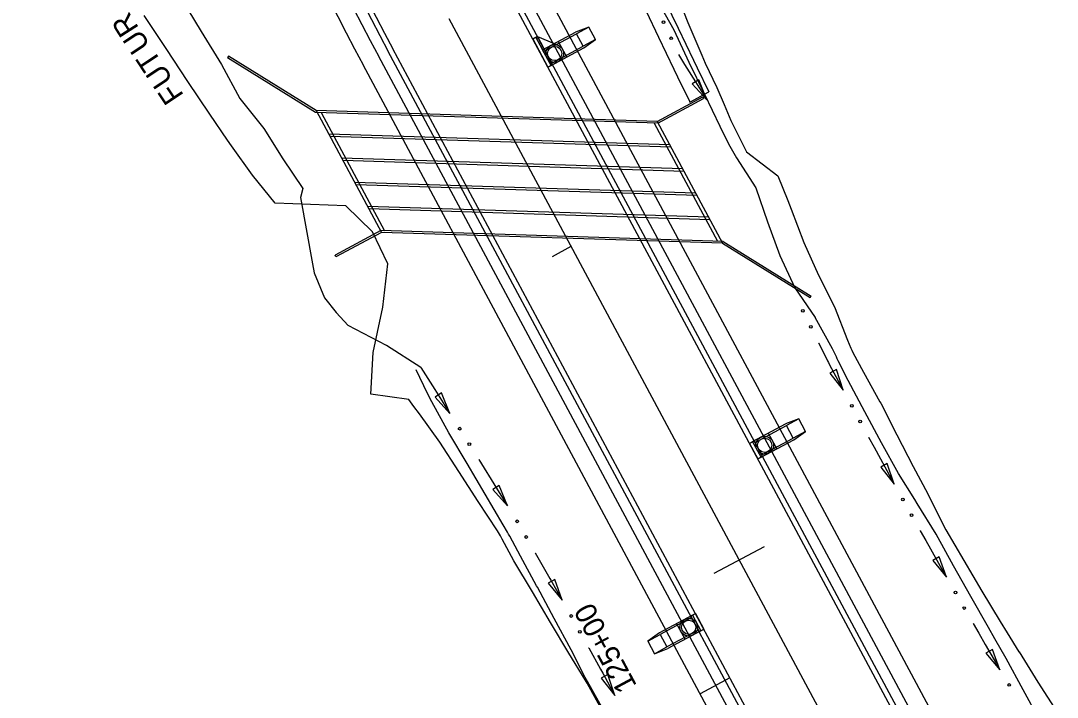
# Model space of a CAD drawing. Extents: x 979959 to 994833, y 1835619 to 1845316.
# Drawn here: x 992472.4 to 992763.9, y 1841250.8 to 1841441.1 of the extents above; entities that cross this region are included whole.
import ezdxf

# ---------------------------------------------------------------- set-up
doc = ezdxf.new("R2010")
doc.units = 0
for name, color, linetype in [('Future 5 Lane Construction Limits', 7, 'Continuous'), ('R_Drainage', 7, 'Continuous'), ('R_Horz Alg', 7, 'Continuous'), ('R_Horz Alg Stationing', 7, 'Continuous'), ('R_Proposed Const Limits', 7, 'Continuous'), ('R_Proposed Road', 7, 'Continuous'), ('R_Special Ditch', 7, 'Continuous')]:
    doc.layers.add(name, color=color, linetype=linetype)

msp = doc.modelspace()

# ---------------------------------------------------------------- linework, layer by layer
at = {"layer": 'Future 5 Lane Construction Limits'}
for points in [[(992631, 1841510.9), (992632.44, 1841501.52), (992636.1, 1841493.15), (992638.98, 1841484.37), (992641.67, 1841475.45), (992643.86, 1841468.2), (992644.48, 1841466.3), (992647.7, 1841456.68), (992651.16, 1841447.19), (992656.08, 1841438.48), (992660.28, 1841429.38), (992664.69, 1841420.4), (992669, 1841411.37), (992671.46, 1841406.41), (992673.66, 1841402.52), (992679.08, 1841394.08), (992682.42, 1841384.52), (992685.84, 1841375.01), (992690.13, 1841365.96), (992695.81, 1841357.66)], [(992581.51, 1841334.6), (992570.85, 1841336.06), (992571.49, 1841347.75), (992572.72, 1841353.48), (992574.19, 1841360.54), (992575.68, 1841372.69), (992571.33, 1841381.7), (992563.83, 1841389.03), (992544, 1841389.75), (992537.6, 1841397.66), (992531.71, 1841405.85), (992530.57, 1841407.47), (992525.58, 1841414.75), (992519.42, 1841423.97), (992513.27, 1841433.23), (992507.09, 1841442.53)], [(992758.91, 1841244.47), (992754.31, 1841252.9), (992749.53, 1841261.73), (992746.36, 1841267.28), (992744.53, 1841270.47), (992739.6, 1841279.15), (992734.71, 1841287.83), (992729.85, 1841296.69), (992724.5, 1841305.33), (992723.79, 1841306.46), (992719.26, 1841313.73), (992714.49, 1841322.33), (992709.8, 1841331.11), (992705.11, 1841339.89), (992702.31, 1841345.42), (992702.04, 1841345.98), (992701.77, 1841346.55), (992700.65, 1841348.83), (992695.81, 1841357.66)], [(992640.53, 1841238.67), (992636.4, 1841246.3), (992631.71, 1841254.81), (992631.15, 1841255.72), (992626.52, 1841263.21), (992621.4, 1841271.89), (992616.28, 1841280.46), (992611.03, 1841289.24), (992607.77, 1841295.28), (992607.35, 1841296.2), (992607.34, 1841296.2), (992606.47, 1841297.62), (992601.08, 1841305.92), (992595.61, 1841314.31), (992590.23, 1841322.53), (992584.52, 1841330.5), (992582.98, 1841332.59), (992581.51, 1841334.6)]]:
    msp.add_lwpolyline(points, dxfattribs=at)
at = {"layer": 'R_Drainage'}
for p, q in [((992619.17, 1841432.87), (992628.43, 1841437.83)), ((992632.19, 1841439.28), (992628.43, 1841437.83)), ((992632.19, 1841439.28), (992628.66, 1841437.39)), ((992634.08, 1841435.76), (992632.19, 1841439.28)), ((992617.28, 1841436.4), (992621.53, 1841428.47)), ((992621.53, 1841428.47), (992617.28, 1841436.4)), ((992617.72, 1841436.63), (992623.54, 1841434.15)), ((992617.72, 1841436.63), (992622.43, 1841434.62)), ((992619.85, 1841432.67), (992628.66, 1841437.39)), ((992623.58, 1841435.24), (992625.94, 1841430.83)), ((992630.55, 1841433.87), (992628.66, 1841437.39)), ((992634.08, 1841435.76), (992630.55, 1841433.87)), ((992630.78, 1841433.42), (992634.08, 1841435.76)), ((992621.74, 1841429.14), (992619.85, 1841432.67)), ((992621.53, 1841428.47), (992630.78, 1841433.42)), ((992621.74, 1841429.14), (992630.55, 1841433.87)), ((992530.82, 1841431.08), (992530.55, 1841430.65)), ((992555.31, 1841415.3), (992530.55, 1841430.65)), ((992555.46, 1841415.8), (992530.82, 1841431.08)), ((992660.59, 1841418.2), (992665.88, 1841421.04)), ((992651.41, 1841412.77), (992664.19, 1841419.62)), ((992651.53, 1841412.26), (992664.43, 1841419.18)), ((992664.19, 1841419.62), (992664.43, 1841419.18)), ((992651.53, 1841412.26), (992555.31, 1841415.3)), ((992555.46, 1841415.8), (992573.83, 1841381.53)), ((992651.41, 1841412.77), (992555.46, 1841415.8)), ((992556.89, 1841415.25), (992574.71, 1841382.01)), ((992650.53, 1841412.3), (992668.35, 1841379.05)), ((992651.41, 1841412.77), (992669.78, 1841378.51)), ((992654.96, 1841406.15), (992559.01, 1841409.18)), ((992655.32, 1841405.48), (992559.37, 1841408.5)), ((992658.6, 1841399.37), (992562.65, 1841402.4)), ((992658.96, 1841398.69), (992563.01, 1841401.72)), ((992662.23, 1841392.58), (992566.28, 1841395.61)), ((992662.6, 1841391.91), (992566.65, 1841394.93)), ((992665.87, 1841385.8), (992569.92, 1841388.83)), ((992666.24, 1841385.12), (992570.28, 1841388.15)), ((992573.71, 1841382.04), (992560.81, 1841375.12)), ((992573.83, 1841381.53), (992561.05, 1841374.68)), ((992669.93, 1841379), (992573.71, 1841382.04)), ((992669.78, 1841378.51), (992573.83, 1841381.53)), ((992669.78, 1841378.51), (992694.43, 1841363.22)), ((992669.93, 1841379), (992694.69, 1841363.65)), ((992561.05, 1841374.68), (992560.81, 1841375.12)), ((992694.43, 1841363.22), (992694.69, 1841363.65)), ((992678.23, 1841322.71), (992687.48, 1841327.67)), ((992678.9, 1841322.5), (992687.72, 1841327.23)), ((992691.24, 1841329.12), (992687.48, 1841327.67)), ((992691.24, 1841329.12), (992687.72, 1841327.23)), ((992689.61, 1841323.7), (992687.72, 1841327.23)), ((992693.13, 1841325.59), (992691.24, 1841329.12)), ((992682.63, 1841325.07), (992685, 1841320.66)), ((992693.13, 1841325.59), (992689.61, 1841323.7)), ((992689.84, 1841323.26), (992693.13, 1841325.59)), ((992678.67, 1841322.94), (992677.34, 1841322.23)), ((992680.59, 1841318.3), (992678.23, 1841322.71)), ((992680.79, 1841318.98), (992678.9, 1841322.5)), ((992680.59, 1841318.3), (992689.84, 1841323.26)), ((992680.79, 1841318.98), (992689.61, 1841323.7)), ((992661.27, 1841273.91), (992652.02, 1841268.95)), ((992661.07, 1841273.23), (992652.25, 1841268.51)), ((992661.07, 1841273.23), (992662.96, 1841269.71)), ((992661.27, 1841273.91), (992663.63, 1841269.5)), ((992652.02, 1841268.95), (992648.73, 1841266.62)), ((992662.96, 1841269.71), (992654.14, 1841264.98)), ((992663.63, 1841269.5), (992654.38, 1841264.54)), ((992659.22, 1841267.14), (992656.86, 1841271.54)), ((992663.19, 1841269.26), (992664.51, 1841269.97)), ((992648.73, 1841266.62), (992652.25, 1841268.51)), ((992648.73, 1841266.62), (992650.62, 1841263.09)), ((992652.25, 1841268.51), (992654.14, 1841264.98)), ((992650.62, 1841263.09), (992654.14, 1841264.98)), ((992650.62, 1841263.09), (992654.38, 1841264.54))]:
    msp.add_line(p, q, dxfattribs=at)
for points in [[(992613.97, 1841543.61), (992618.65, 1841535.4), (992621.39, 1841526.27), (992624.19, 1841517.55), (992627.16, 1841508.86), (992627.89, 1841506.81), (992630.28, 1841500.24), (992633.57, 1841491.66), (992637.02, 1841483.14), (992640.64, 1841474.68), (992644.5, 1841466.09), (992648.71, 1841457.03), (992652.96, 1841447.97), (992653.76, 1841446.27), (992657.24, 1841438.94), (992661.57, 1841429.93), (992662.61, 1841427.78), (992665.88, 1841421.04)], [(992660.59, 1841418.2), (992660.54, 1841418.31), (992657.21, 1841425.16), (992656.16, 1841427.32), (992651.83, 1841436.36), (992648.34, 1841443.7), (992647.53, 1841445.42), (992643.27, 1841454.49), (992639.04, 1841463.6), (992635.14, 1841472.27), (992631.48, 1841480.83), (992627.99, 1841489.46), (992624.66, 1841498.14), (992622.24, 1841504.78), (992621.49, 1841506.88), (992618.5, 1841515.66), (992615.66, 1841524.49), (992613.1, 1841533.02), (992608.61, 1841540.89)], [(992677.34, 1841322.23), (992679.71, 1841317.83), (992681.03, 1841318.54), (992678.67, 1841322.94)], [(992664.51, 1841269.97), (992662.15, 1841274.38), (992660.83, 1841273.67), (992663.19, 1841269.26)]]:
    msp.add_lwpolyline(points, dxfattribs=at)
for points in [[(992617.72, 1841436.63), (992621.98, 1841428.7), (992620.65, 1841427.99), (992616.4, 1841435.93)], [(992621.98, 1841428.7), (992617.72, 1841436.63), (992616.4, 1841435.93), (992620.65, 1841427.99)], [(992623.58, 1841435.24), (992625.94, 1841430.83), (992621.53, 1841428.47), (992619.17, 1841432.87)], [(992682.63, 1841325.07), (992685, 1841320.66), (992680.59, 1841318.3), (992678.23, 1841322.71)], [(992678.67, 1841322.94), (992681.03, 1841318.54), (992679.71, 1841317.83), (992677.34, 1841322.23)], [(992659.22, 1841267.14), (992656.86, 1841271.54), (992661.27, 1841273.91), (992663.63, 1841269.5)], [(992663.19, 1841269.26), (992660.83, 1841273.67), (992662.15, 1841274.38), (992664.51, 1841269.97)]]:
    msp.add_lwpolyline(points, close=True, dxfattribs=at)
for centre, radius in [((992622.56, 1841431.85), 2.5), ((992622.56, 1841431.85), 2.5), ((992622.56, 1841431.85), 2), ((992622.56, 1841431.85), 2), ((992681.61, 1841321.69), 2.5), ((992681.61, 1841321.69), 2.5), ((992681.61, 1841321.69), 2), ((992681.61, 1841321.69), 2), ((992660.25, 1841270.52), 2.5), ((992660.25, 1841270.52), 2.5), ((992660.25, 1841270.52), 2), ((992660.25, 1841270.52), 2)]:
    msp.add_circle(centre, radius, dxfattribs=at)
at = {"layer": 'R_Horz Alg'}
msp.add_line((992721.09, 1841202.52), (992592.92, 1841441.62), dxfattribs=at)
at = {"layer": 'R_Horz Alg Stationing'}
for points in [[(992621.94, 1841374.79), (992627.23, 1841377.63)], [(992667.42, 1841285.71), (992681.52, 1841293.27)]]:
    msp.add_lwpolyline(points, dxfattribs=at)
at = {"layer": 'R_Proposed Const Limits'}
for points in [[(992472.41, 1841535.7), (992476.48, 1841525.43), (992481.41, 1841515.48), (992486.58, 1841505.66), (992491.29, 1841495.7), (992496.3, 1841485.89), (992501.34, 1841476.12), (992506.36, 1841466.36), (992511.51, 1841456.69), (992512.89, 1841454.45), (992517.48, 1841447.42), (992523.16, 1841438.06), (992528.82, 1841428.72), (992534, 1841419.16), (992540.79, 1841410.71), (992546.09, 1841402.21), (992551.77, 1841393.91)], [(992656.3, 1841449.94), (992660.01, 1841440.59), (992663.9, 1841431.33), (992664.89, 1841429.14), (992668.11, 1841422.24), (992670.26, 1841417.53), (992672.08, 1841413.01), (992676.49, 1841404.16), (992685.34, 1841397.43), (992688.09, 1841390.52), (992689.04, 1841388.07), (992692.66, 1841378.67), (992696.76, 1841369.52), (992701.25, 1841360.58), (992704.92, 1841351.2), (992705.82, 1841348.97), (992706.08, 1841348.41), (992706.36, 1841347.79), (992709.4, 1841342.25), (992714, 1841333.93), (992714.23, 1841333.5), (992718.76, 1841324.58), (992723.32, 1841315.68), (992727.45, 1841308.04), (992728.03, 1841306.85), (992732.57, 1841297.94), (992737.62, 1841289.3), (992742.63, 1841280.64), (992747.87, 1841272.1), (992749.8, 1841268.97), (992753.1, 1841263.65), (992753.14, 1841263.59), (992758.46, 1841255.09), (992763.89, 1841246.65)], [(992551.77, 1841393.91), (992551.06, 1841391.39), (992554.46, 1841372.66), (992554.92, 1841370.19), (992557.84, 1841363.13), (992561.15, 1841359.04), (992564.48, 1841355.34)], [(992584.88, 1841343.58), (992575.26, 1841349.77), (992564.48, 1841355.34)], [(992639.21, 1841241.8), (992636.63, 1841246.51), (992631.76, 1841255.25), (992631.16, 1841256.42), (992627.24, 1841264.17), (992622.45, 1841272.95), (992617.71, 1841281.76), (992617.48, 1841282.19), (992612.95, 1841290.55), (992609.93, 1841296.1), (992609.6, 1841296.7), (992609.31, 1841297.23), (992608.1, 1841299.3), (992603.04, 1841307.93), (992597.93, 1841316.54), (992592.8, 1841325.14), (992588.02, 1841333.92), (992586.77, 1841336.21), (992583.65, 1841342.92)]]:
    msp.add_lwpolyline(points, dxfattribs=at)
at = {"layer": 'R_Proposed Road'}
for p, q in [((992745.33, 1841215.51), (992617.16, 1841454.62)), ((992736.96, 1841211.03), (992608.79, 1841450.13)), ((992738.28, 1841211.73), (992610.11, 1841450.84)), ((992740.92, 1841213.15), (992612.75, 1841452.25)), ((992703.91, 1841193.31), (992575.74, 1841432.41)), ((992705.23, 1841194.02), (992577.06, 1841433.12)), ((992701.26, 1841191.89), (992573.09, 1841430.99)), ((992696.86, 1841189.53), (992568.69, 1841428.63)), ((992671.84, 1841256.31), (992663.47, 1841251.82))]:
    msp.add_line(p, q, dxfattribs=at)
for radius in [738.7, 735.7, 734.2, 743.7]:
    msp.add_arc((993224.15, 1841779.99), radius, 183.02281, 208.19343, dxfattribs=at)
at = {"layer": 'R_Special Ditch'}
for p, q in [((992663.05, 1841424.46), (992661.26, 1841423.33)), ((992661.26, 1841423.33), (992665.36, 1841418.82)), ((992665.36, 1841418.82), (992663.05, 1841424.46)), ((992701.79, 1841342.97), (992699.92, 1841341.97)), ((992699.92, 1841341.97), (992703.68, 1841337.17)), ((992703.68, 1841337.17), (992701.79, 1841342.97)), ((992590.73, 1841336.42), (992588.91, 1841335.26)), ((992593.09, 1841330.66), (992590.73, 1841336.42)), ((992588.91, 1841335.26), (992593.09, 1841330.66)), ((992716.08, 1841316.56), (992714.23, 1841315.54)), ((992714.23, 1841315.54), (992718.04, 1841310.79)), ((992718.04, 1841310.79), (992716.08, 1841316.56)), ((992606.99, 1841310.42), (992605.15, 1841309.29)), ((992609.28, 1841304.64), (992606.99, 1841310.42)), ((992605.15, 1841309.29), (992609.28, 1841304.64)), ((992730.7, 1841290.34), (992728.86, 1841289.29)), ((992728.86, 1841289.29), (992732.73, 1841284.59)), ((992732.73, 1841284.59), (992730.7, 1841290.34)), ((992622.56, 1841283.98), (992620.68, 1841282.92)), ((992624.63, 1841278.12), (992622.56, 1841283.98)), ((992620.68, 1841282.92), (992624.63, 1841278.12)), ((992745.65, 1841264.3), (992743.82, 1841263.23)), ((992743.82, 1841263.23), (992747.76, 1841258.58)), ((992747.76, 1841258.58), (992745.65, 1841264.3)), ((992637.51, 1841257.21), (992635.62, 1841256.17)), ((992639.5, 1841251.32), (992637.51, 1841257.21)), ((992635.62, 1841256.17), (992639.5, 1841251.32))]:
    msp.add_line(p, q, dxfattribs=at)
for points in [[(992657.37, 1841431.52), (992659.1, 1841428.75), (992660.37, 1841426.73), (992664.44, 1841420.28), (992665.36, 1841418.83)], [(992657.44, 1841431.6), (992657.45, 1841431.57)], [(992696.77, 1841350.53), (992696.79, 1841350.5)], [(992696.79, 1841350.5), (992698.22, 1841347.61), (992699.29, 1841345.47), (992699.57, 1841344.92), (992699.87, 1841344.32), (992702.85, 1841338.74), (992703.69, 1841337.18)], [(992584.88, 1841343.58), (992588.87, 1841337.33), (992590.27, 1841335.13), (992593.09, 1841330.66)], [(992710.82, 1841323.98), (992710.84, 1841323.95)], [(992710.84, 1841323.95), (992712.36, 1841321.15), (992717.17, 1841312.38), (992718.05, 1841310.79)], [(992601.22, 1841317.7), (992601.24, 1841317.66)], [(992601.24, 1841317.66), (992606.21, 1841309.63), (992609.28, 1841304.64)], [(992725.34, 1841297.69), (992725.36, 1841297.66)], [(992725.36, 1841297.66), (992726.9, 1841294.91), (992731.83, 1841286.2), (992732.74, 1841284.6)], [(992617.06, 1841291.46), (992617.08, 1841291.43)], [(992617.08, 1841291.43), (992621.2, 1841284.19), (992621.45, 1841283.76), (992624.63, 1841278.12)], [(992740.2, 1841271.58), (992740.22, 1841271.55)], [(992740.22, 1841271.55), (992741.79, 1841268.84), (992743.63, 1841265.66), (992746.78, 1841260.26), (992746.82, 1841260.2), (992747.77, 1841258.59)], [(992632.1, 1841264.76), (992632.12, 1841264.73)], [(992632.12, 1841264.73), (992635.45, 1841258.72), (992636.08, 1841257.57), (992639.5, 1841251.32)]]:
    msp.add_lwpolyline(points, dxfattribs=at)
for centre, radius in [((992653.16, 1841440.64), 0.375), ((992655.31, 1841436.11), 0.375), ((992692.37, 1841359.5), 0.375), ((992694.59, 1841355.01), 0.375), ((992706.09, 1841332.79), 0.375), ((992708.47, 1841328.38), 0.375), ((992595.84, 1841326.36), 0.383), ((992598.55, 1841322.03), 0.383), ((992720.5, 1841306.43), 0.375), ((992722.94, 1841302.06), 0.375), ((992611.98, 1841300.3), 0.383), ((992614.56, 1841295.89), 0.383), ((992735.26, 1841280.27), 0.375), ((992737.75, 1841275.92), 0.375), ((992627.17, 1841273.68), 0.383), ((992629.66, 1841269.22), 0.383), ((992750.34, 1841254.29), 0.375)]:
    msp.add_circle(centre, radius, dxfattribs=at)

# ---------------------------------------------------------------- texts
at = {"layer": 'Future 5 Lane Construction Limits'}
for s, rotation, p in [('R', 122.6237, (992505.78, 1841439.01)), ('U', 123.5916, (992509, 1841434.23)), ('T', 123.5916, (992512.24, 1841429.35)), ('U', 123.6014, (992515.43, 1841424.55)), ('F', 123.7265, (992518.42, 1841420.07))]:
    msp.add_text(s, height=6, rotation=rotation, dxfattribs=at).set_placement(p)
at = {"layer": 'R_Horz Alg Stationing'}
msp.add_text('125+00', height=6, rotation=118.1934, dxfattribs=at).set_placement((992645.79, 1841254.1))

doc.saveas('drawing.dxf')
